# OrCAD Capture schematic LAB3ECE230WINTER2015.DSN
size A
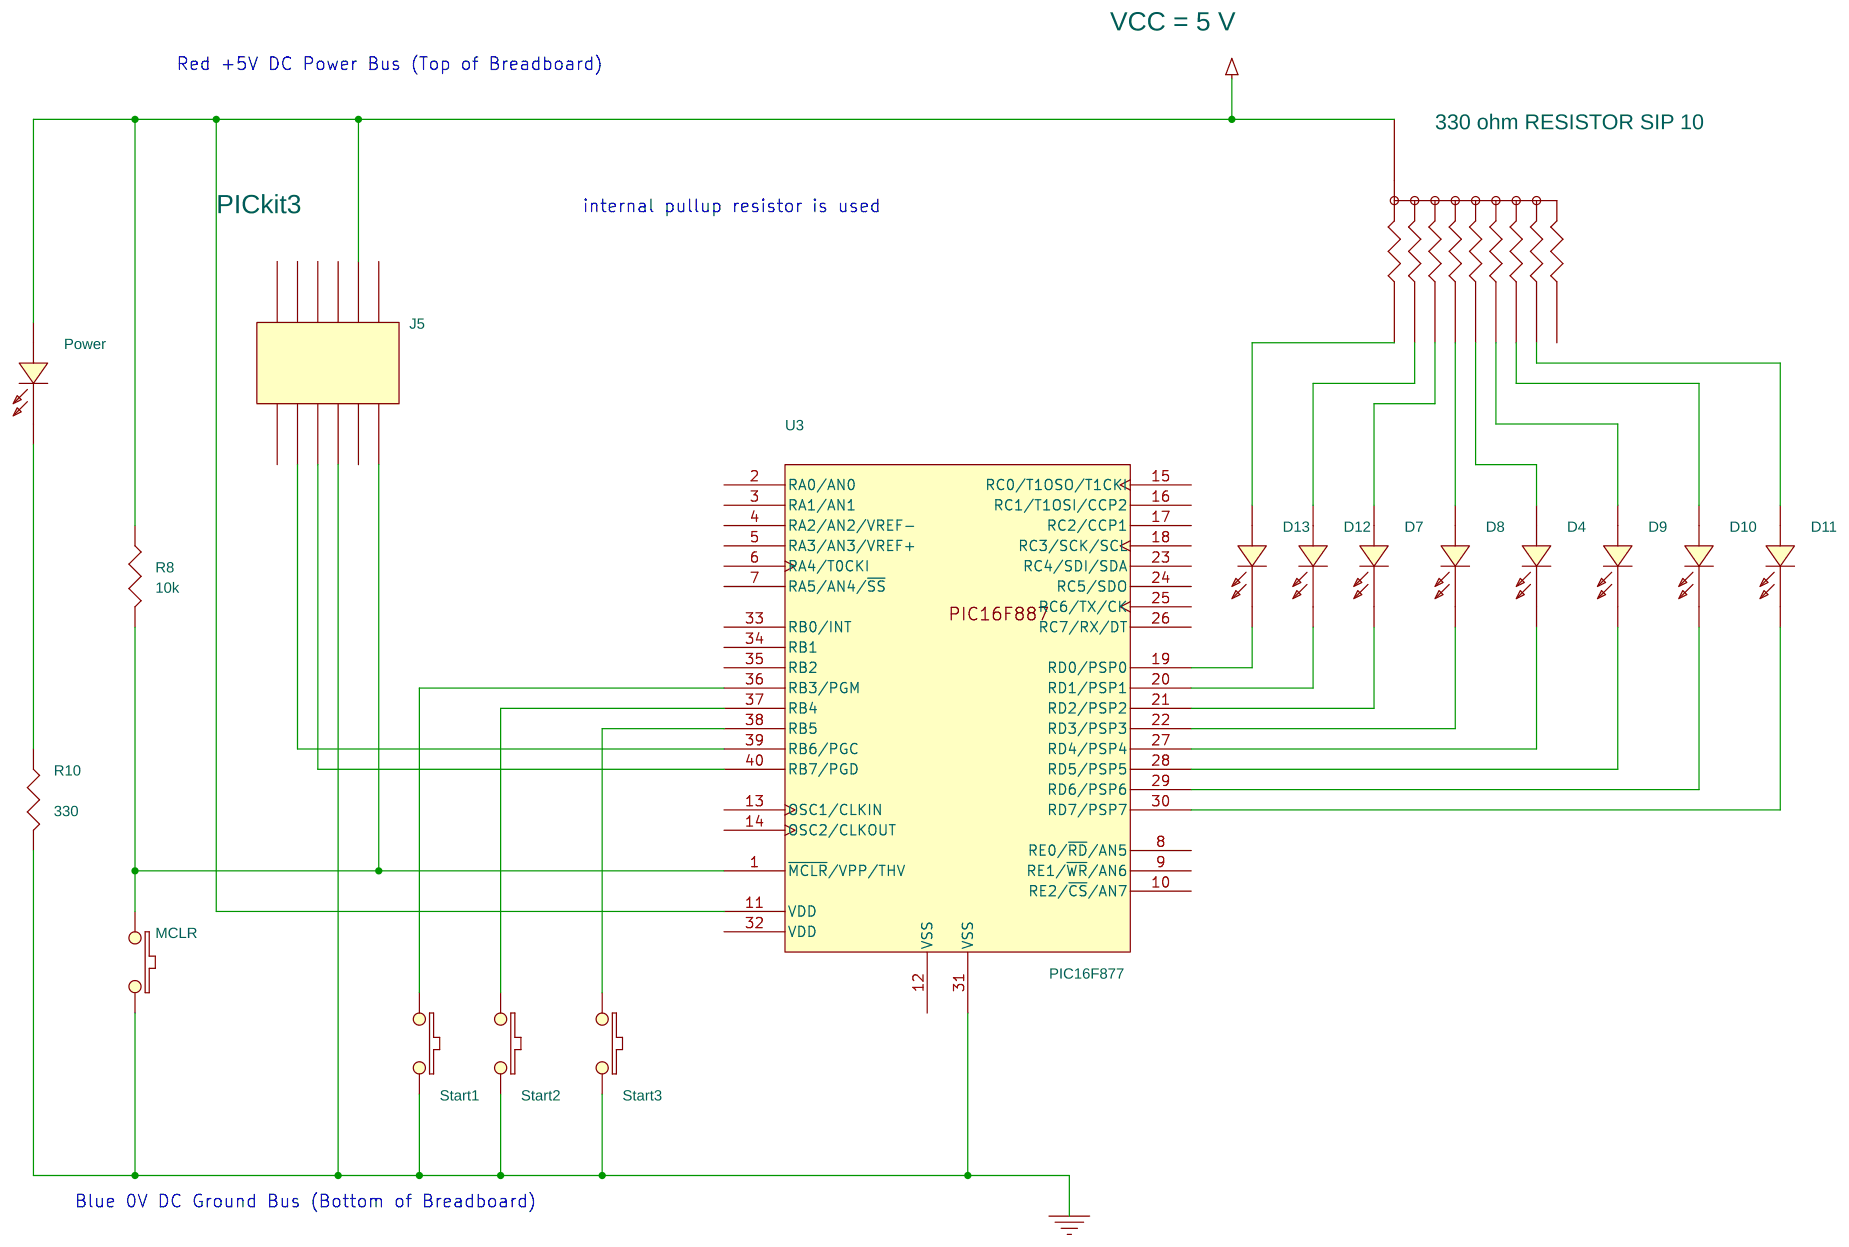
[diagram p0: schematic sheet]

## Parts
D4  Interrupt LED
D7  Interrupt LED
D8  Interrupt LED
D9  Interrupt LED
D10  Interrupt LED
D11  Interrupt LED
D12  Interrupt LED
D13  Interrupt LED
J5  PICkit3
MCLR  SW PUSHBUTTON
Power  5VDC
R8  10k
R10  330
R11  330 ohm RESISTOR SIP 10
Start1  SW PUSHBUTTON
Start2  SW PUSHBUTTON
Start3  SW PUSHBUTTON
U3  PIC16F877

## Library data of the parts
D4 D7-D13 Power = LED
J5 = CONNECTOR_EDGE_6x2_0
MCLR Start1-Start3 = SW_PUSHBUTTON
R8 R10 = RESISTOR
R11 = RESISTOR_SIP_10
U3 = PIC16F877_3

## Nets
GND: J5.3 MCLR.2 R10.2 Start1.2 Start2.2 Start3.2 U3.31(VSS)
Vcc = 5 V: J5.2 Power.1(ANODE) R8.1 R11.1 U3.11(VDD)
VDD: U3.32(VDD)
N1027338: D7.2(CATHODE) U3.21(RD2/PSP2)
N1027370: D8.2(CATHODE) U3.22(RD3/PSP3)
N1027374: D9.2(CATHODE) U3.28(RD5/PSP5)
N1027406: D11.2(CATHODE) U3.30(RD7/PSP7)
N1027424: D12.2(CATHODE) U3.20(RD1/PSP1)
N1027442: D13.2(CATHODE) U3.19(RD0/PSP0)
N1027476: D4.2(CATHODE) U3.27(RD4/PSP4)
N1027484: D10.2(CATHODE) U3.29(RD6/PSP6)
N1027530: D13.1(ANODE) R11.2
N1027534: D12.1(ANODE) R11.3
N1027550: D7.1(ANODE) R11.4
N1027562: D8.1(ANODE) R11.5
N1027566: D4.1(ANODE) R11.6
N1027578: D9.1(ANODE) R11.7
N1027590: D10.1(ANODE) R11.8
N1027602: D11.1(ANODE) R11.9
N1027668: Start3.1 U3.38(RB5)
N1027676: Start2.1 U3.37(RB4)
N1027684: Start1.1 U3.36(RB3/PGM)
N1027706: J5.1 MCLR.1 R8.2 U3.1(~{MCLR}/VPP/THV)
N1027714: Power.2(CATHODE) R10.1
N1027834: J5.5 U3.39(RB6/PGC)
N1027854: J5.4 U3.40(RB7/PGD)

Not connected (* = marked no-connect by the designer): J5 6; R11 10; U3 2(RA0/AN0) 3(RA1/AN1) 4(RA2/AN2/VREF-) 5(RA3/AN3/VREF+) 6(RA4/T0CKI) 7(RA5/AN4/~{SS}) 8(RE0/~{RD}/AN5) 9(RE1/~{WR}/AN6) 10(RE2/~{CS}/AN7) 12(VSS) 13(OSC1/CLKIN) 14(OSC2/CLKOUT) 15(RC0/T1OSO/T1CKI) 16(RC1/T1OSI/CCP2) 17(RC2/CCP1) 18(RC3/SCK/SCL) 23(RC4/SDI/SDA) 24(RC5/SDO) 25(RC6/TX/CK) 26(RC7/RX/DT) 33(RB0/INT) 34(RB1) 35(RB2)

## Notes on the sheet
- Red +5V DC Power Bus (Top of Breadboard)
- internal pullup resistor is used
- Blue 0V DC Ground Bus (Bottom of Breadboard)
